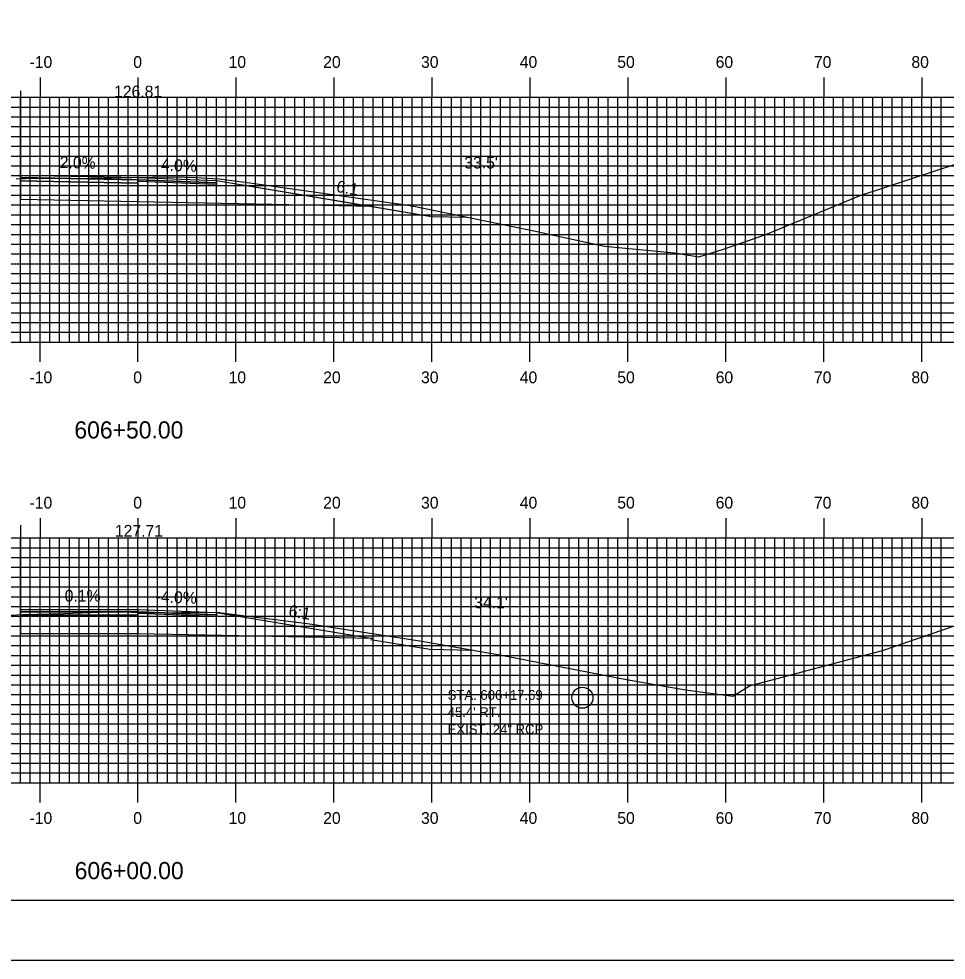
# Model space of a CAD drawing. Extents: x 842569 to 842912, y 363538 to 363758.
# Drawn here: x 842722.2 to 842816.9, y 363537.6 to 363633.7 of the extents above; entities that cross this region are included whole.
import ezdxf

# ---------------------------------------------------------------- set-up
doc = ezdxf.new("R2010")
doc.units = 0
for name, color, linetype in [('ANNOTATION', 7, 'Continuous'), ('BORDER', 7, 'Continuous'), ('D_Drainage_Culvert', 7, 'Continuous'), ('D_Roadway_Centerline', 7, 'Continuous'), ('D_Roadway_Centerline_Text', 7, 'Continuous'), ('D_Roadway_Edge_Shoulder', 7, 'Continuous'), ('D_Roadway_Edge_TW', 7, 'Continuous'), ('D_Roadway_FinishedGrade', 7, 'Continuous'), ('D_Roadway_Pavement', 7, 'Continuous'), ('D_Roadway_SlopeLines', 7, 'Continuous'), ('D_Roadway_SubGrade', 7, 'Continuous'), ('D_Text_Monospaced', 7, 'Continuous'), ('D_Text_Standard', 7, 'Continuous'), ('H_V ANNOTATION', 7, 'Continuous'), ('M_Roadway_Centerline', 7, 'Continuous'), ('MAJOR', 7, 'Continuous'), ('MINOR', 7, 'Continuous'), ('PLOT BOUNDARY', 7, 'Continuous'), ('S_Roadway_Centerline', 7, 'Continuous')]:
    doc.layers.add(name, color=color, linetype=linetype)

msp = doc.modelspace()

# ---------------------------------------------------------------- linework, layer by layer
at = {"layer": 'BORDER'}
msp.add_lwpolyline([(842584.798, 363543.721), (842904.798, 363543.721), (842904.798, 363753.721), (842584.798, 363753.721)], close=True, dxfattribs=at)
at = {"layer": 'D_Drainage_Culvert'}
msp.add_circle((842779.767, 363564.404), 1.074, dxfattribs=at)
at = {"layer": 'D_Roadway_Centerline'}
for points in [[(842722.398, 363617.776), (842734.398, 363617.536), (842742.398, 363617.216), (842758.352, 363614.557), (842764.352, 363613.557)], [(842722.398, 363573.413), (842734.398, 363573.429), (842742.398, 363573.109), (842758.352, 363570.45)]]:
    msp.add_lwpolyline(points, dxfattribs=at)
at = {"layer": 'D_Roadway_Edge_Shoulder'}
for points in [[(842734.398, 363617.536), (842742.398, 363617.216), (842742.398, 363616.966), (842734.398, 363617.286)], [(842734.398, 363573.429), (842742.398, 363573.109), (842742.398, 363572.859), (842734.398, 363573.179)]]:
    msp.add_lwpolyline(points, close=True, dxfattribs=at)
at = {"layer": 'D_Roadway_Edge_TW'}
for points in [[(842722.398, 363617.776), (842734.398, 363617.536), (842734.398, 363617.286), (842722.398, 363617.526)], [(842722.398, 363573.413), (842734.398, 363573.429), (842734.398, 363573.179), (842722.398, 363573.163)]]:
    msp.add_lwpolyline(points, close=True, dxfattribs=at)
for points in [[(842722.398, 363617.776), (842722.398, 363617.526)], [(842722.398, 363573.413), (842722.398, 363573.163)]]:
    msp.add_lwpolyline(points, dxfattribs=at)
at = {"layer": 'D_Roadway_FinishedGrade'}
for points in [[(842758.352, 363614.557), (842764.352, 363613.557), (842767.934, 363613.485)], [(842758.179, 363570.358), (842764.179, 363569.358), (842768.466, 363569.272)]]:
    msp.add_lwpolyline(points, dxfattribs=at)
at = {"layer": 'D_Roadway_Pavement'}
for points in [[(842722.398, 363617.526), (842722.398, 363617.193)], [(842734.398, 363617.286), (842734.398, 363616.953)], [(842734.398, 363617.286), (842734.398, 363616.953)], [(842722.398, 363573.163), (842722.398, 363572.83)], [(842734.398, 363573.179), (842734.398, 363572.845)], [(842734.398, 363573.179), (842734.398, 363572.845)]]:
    msp.add_lwpolyline(points, dxfattribs=at)
for points in [[(842722.398, 363617.526), (842734.398, 363617.286), (842734.398, 363616.953), (842722.398, 363617.193)], [(842734.398, 363617.286), (842742.398, 363616.966), (842742.398, 363616.799), (842734.398, 363617.119)], [(842722.398, 363573.163), (842734.398, 363573.179), (842734.398, 363572.845), (842722.398, 363572.83)], [(842734.398, 363573.179), (842742.398, 363572.859), (842742.398, 363572.692), (842734.398, 363573.012)]]:
    msp.add_lwpolyline(points, close=True, dxfattribs=at)
at = {"layer": 'D_Roadway_SlopeLines'}
msp.add_lwpolyline([(842742.398, 363617.216), (842764.352, 363613.557)], dxfattribs=at)
at = {"layer": 'D_Roadway_SubGrade'}
for p, q in [((842722.398, 363626.373), (842722.398, 363615.276)), ((842722.398, 363582.011), (842722.398, 363570.913))]:
    msp.add_line(p, q, dxfattribs=at)
for points in [[(842722.398, 363617.193), (842722.398, 363615.276)], [(842722.398, 363572.83), (842722.398, 363570.913)]]:
    msp.add_lwpolyline(points, dxfattribs=at)
for points in [[(842722.398, 363617.193), (842734.398, 363616.953), (842734.398, 363615.036), (842722.398, 363615.276)], [(842734.398, 363616.953), (842734.398, 363617.286), (842742.398, 363616.966), (842742.398, 363617.216), (842758.352, 363614.557), (842734.398, 363615.036)], [(842722.398, 363572.83), (842734.398, 363572.845), (842734.398, 363570.929), (842722.398, 363570.913)], [(842734.398, 363572.845), (842734.398, 363573.179), (842742.398, 363572.859), (842742.398, 363573.109), (842758.352, 363570.45), (842734.398, 363570.929)]]:
    msp.add_lwpolyline(points, close=True, dxfattribs=at)
at = {"layer": 'MAJOR'}
for p, q in [((842724.398, 363627.725), (842724.398, 363625.721)), ((842734.398, 363627.725), (842734.398, 363625.721)), ((842744.398, 363627.725), (842744.398, 363625.721)), ((842754.398, 363627.725), (842754.398, 363625.721)), ((842764.398, 363627.725), (842764.398, 363625.721)), ((842774.398, 363627.725), (842774.398, 363625.721)), ((842784.398, 363627.725), (842784.398, 363625.721)), ((842794.398, 363627.725), (842794.398, 363625.721)), ((842804.398, 363627.725), (842804.398, 363625.721)), ((842814.398, 363627.725), (842814.398, 363625.721)), ((842594.398, 363625.721), (842874.398, 363625.721)), ((842594.398, 363625.721), (842874.398, 363625.721)), ((842724.398, 363600.721), (842724.398, 363625.721)), ((842734.398, 363600.721), (842734.398, 363625.721)), ((842744.398, 363600.721), (842744.398, 363625.721)), ((842754.398, 363600.721), (842754.398, 363625.721)), ((842764.398, 363600.721), (842764.398, 363625.721)), ((842774.398, 363600.721), (842774.398, 363625.721)), ((842784.398, 363600.721), (842784.398, 363625.721)), ((842794.398, 363600.721), (842794.398, 363625.721)), ((842804.398, 363600.721), (842804.398, 363625.721)), ((842814.398, 363600.721), (842814.398, 363625.721)), ((842594.398, 363620.721), (842874.398, 363620.721)), ((842594.398, 363615.721), (842874.398, 363615.721)), ((842594.398, 363610.721), (842874.398, 363610.721)), ((842594.398, 363605.721), (842874.398, 363605.721)), ((842594.398, 363600.721), (842874.398, 363600.721)), ((842594.398, 363600.721), (842874.398, 363600.721)), ((842724.398, 363598.717), (842724.398, 363600.721)), ((842734.398, 363598.717), (842734.398, 363600.721)), ((842744.398, 363598.717), (842744.398, 363600.721)), ((842754.398, 363598.717), (842754.398, 363600.721)), ((842764.398, 363598.717), (842764.398, 363600.721)), ((842774.398, 363598.717), (842774.398, 363600.721)), ((842784.398, 363598.717), (842784.398, 363600.721)), ((842794.398, 363598.717), (842794.398, 363600.721)), ((842804.398, 363598.717), (842804.398, 363600.721)), ((842814.398, 363598.717), (842814.398, 363600.721)), ((842724.398, 363582.725), (842724.398, 363580.721)), ((842734.398, 363582.725), (842734.398, 363580.721)), ((842744.398, 363582.725), (842744.398, 363580.721)), ((842754.398, 363582.725), (842754.398, 363580.721)), ((842764.398, 363582.725), (842764.398, 363580.721)), ((842774.398, 363582.725), (842774.398, 363580.721)), ((842784.398, 363582.725), (842784.398, 363580.721)), ((842794.398, 363582.725), (842794.398, 363580.721)), ((842804.398, 363582.725), (842804.398, 363580.721)), ((842814.398, 363582.725), (842814.398, 363580.721)), ((842594.398, 363580.721), (842874.398, 363580.721)), ((842594.398, 363580.721), (842874.398, 363580.721)), ((842724.398, 363555.721), (842724.398, 363580.721)), ((842734.398, 363555.721), (842734.398, 363580.721)), ((842744.398, 363555.721), (842744.398, 363580.721)), ((842754.398, 363555.721), (842754.398, 363580.721)), ((842764.398, 363555.721), (842764.398, 363580.721)), ((842774.398, 363555.721), (842774.398, 363580.721)), ((842784.398, 363555.721), (842784.398, 363580.721)), ((842794.398, 363555.721), (842794.398, 363580.721)), ((842804.398, 363555.721), (842804.398, 363580.721)), ((842814.398, 363555.721), (842814.398, 363580.721)), ((842594.398, 363575.721), (842874.398, 363575.721)), ((842594.398, 363570.721), (842874.398, 363570.721)), ((842594.398, 363565.721), (842874.398, 363565.721)), ((842594.398, 363560.721), (842874.398, 363560.721)), ((842594.398, 363555.721), (842874.398, 363555.721)), ((842594.398, 363555.721), (842874.398, 363555.721)), ((842724.398, 363553.717), (842724.398, 363555.721)), ((842734.398, 363553.717), (842734.398, 363555.721)), ((842744.398, 363553.717), (842744.398, 363555.721)), ((842754.398, 363553.717), (842754.398, 363555.721)), ((842764.398, 363553.717), (842764.398, 363555.721)), ((842774.398, 363553.717), (842774.398, 363555.721)), ((842784.398, 363553.717), (842784.398, 363555.721)), ((842794.398, 363553.717), (842794.398, 363555.721)), ((842804.398, 363553.717), (842804.398, 363555.721)), ((842814.398, 363553.717), (842814.398, 363555.721))]:
    msp.add_line(p, q, dxfattribs=at)
at = {"layer": 'MINOR'}
for p, q in [((842722.398, 363600.721), (842722.398, 363625.721)), ((842723.398, 363600.721), (842723.398, 363625.721)), ((842725.398, 363600.721), (842725.398, 363625.721)), ((842726.398, 363600.721), (842726.398, 363625.721)), ((842727.398, 363600.721), (842727.398, 363625.721)), ((842728.398, 363600.721), (842728.398, 363625.721)), ((842729.398, 363600.721), (842729.398, 363625.721)), ((842730.398, 363600.721), (842730.398, 363625.721)), ((842731.398, 363600.721), (842731.398, 363625.721)), ((842732.398, 363600.721), (842732.398, 363625.721)), ((842733.398, 363600.721), (842733.398, 363625.721)), ((842735.398, 363600.721), (842735.398, 363625.721)), ((842736.398, 363600.721), (842736.398, 363625.721)), ((842737.398, 363600.721), (842737.398, 363625.721)), ((842738.398, 363600.721), (842738.398, 363625.721)), ((842739.398, 363600.721), (842739.398, 363625.721)), ((842740.398, 363600.721), (842740.398, 363625.721)), ((842741.398, 363600.721), (842741.398, 363625.721)), ((842742.398, 363600.721), (842742.398, 363625.721)), ((842743.398, 363600.721), (842743.398, 363625.721)), ((842745.398, 363600.721), (842745.398, 363625.721)), ((842746.398, 363600.721), (842746.398, 363625.721)), ((842747.398, 363600.721), (842747.398, 363625.721)), ((842748.398, 363600.721), (842748.398, 363625.721)), ((842749.398, 363600.721), (842749.398, 363625.721)), ((842750.398, 363600.721), (842750.398, 363625.721)), ((842751.398, 363600.721), (842751.398, 363625.721)), ((842752.398, 363600.721), (842752.398, 363625.721)), ((842753.398, 363600.721), (842753.398, 363625.721)), ((842755.398, 363600.721), (842755.398, 363625.721)), ((842756.398, 363600.721), (842756.398, 363625.721)), ((842757.398, 363600.721), (842757.398, 363625.721)), ((842758.398, 363600.721), (842758.398, 363625.721)), ((842759.398, 363600.721), (842759.398, 363625.721)), ((842760.398, 363600.721), (842760.398, 363625.721)), ((842761.398, 363600.721), (842761.398, 363625.721)), ((842762.398, 363600.721), (842762.398, 363625.721)), ((842763.398, 363600.721), (842763.398, 363625.721)), ((842765.398, 363600.721), (842765.398, 363625.721)), ((842766.398, 363600.721), (842766.398, 363625.721)), ((842767.398, 363600.721), (842767.398, 363625.721)), ((842768.398, 363600.721), (842768.398, 363625.721)), ((842769.398, 363600.721), (842769.398, 363625.721)), ((842770.398, 363600.721), (842770.398, 363625.721)), ((842771.398, 363600.721), (842771.398, 363625.721)), ((842772.398, 363600.721), (842772.398, 363625.721)), ((842773.398, 363600.721), (842773.398, 363625.721)), ((842775.398, 363600.721), (842775.398, 363625.721)), ((842776.398, 363600.721), (842776.398, 363625.721)), ((842777.398, 363600.721), (842777.398, 363625.721)), ((842778.398, 363600.721), (842778.398, 363625.721)), ((842779.398, 363600.721), (842779.398, 363625.721)), ((842780.398, 363600.721), (842780.398, 363625.721)), ((842781.398, 363600.721), (842781.398, 363625.721)), ((842782.398, 363600.721), (842782.398, 363625.721)), ((842783.398, 363600.721), (842783.398, 363625.721)), ((842785.398, 363600.721), (842785.398, 363625.721)), ((842786.398, 363600.721), (842786.398, 363625.721)), ((842787.398, 363600.721), (842787.398, 363625.721)), ((842788.398, 363600.721), (842788.398, 363625.721)), ((842789.398, 363600.721), (842789.398, 363625.721)), ((842790.398, 363600.721), (842790.398, 363625.721)), ((842791.398, 363600.721), (842791.398, 363625.721)), ((842792.398, 363600.721), (842792.398, 363625.721)), ((842793.398, 363600.721), (842793.398, 363625.721)), ((842795.398, 363600.721), (842795.398, 363625.721)), ((842796.398, 363600.721), (842796.398, 363625.721)), ((842797.398, 363600.721), (842797.398, 363625.721)), ((842798.398, 363600.721), (842798.398, 363625.721)), ((842799.398, 363600.721), (842799.398, 363625.721)), ((842800.398, 363600.721), (842800.398, 363625.721)), ((842801.398, 363600.721), (842801.398, 363625.721)), ((842802.398, 363600.721), (842802.398, 363625.721)), ((842803.398, 363600.721), (842803.398, 363625.721)), ((842805.398, 363600.721), (842805.398, 363625.721)), ((842806.398, 363600.721), (842806.398, 363625.721)), ((842807.398, 363600.721), (842807.398, 363625.721)), ((842808.398, 363600.721), (842808.398, 363625.721)), ((842809.398, 363600.721), (842809.398, 363625.721)), ((842810.398, 363600.721), (842810.398, 363625.721)), ((842811.398, 363600.721), (842811.398, 363625.721)), ((842812.398, 363600.721), (842812.398, 363625.721)), ((842813.398, 363600.721), (842813.398, 363625.721)), ((842815.398, 363600.721), (842815.398, 363625.721)), ((842816.398, 363600.721), (842816.398, 363625.721)), ((842594.398, 363624.721), (842874.398, 363624.721)), ((842594.398, 363623.721), (842874.398, 363623.721)), ((842594.398, 363622.721), (842874.398, 363622.721)), ((842594.398, 363621.721), (842874.398, 363621.721)), ((842594.398, 363619.721), (842874.398, 363619.721)), ((842594.398, 363618.721), (842874.398, 363618.721)), ((842594.398, 363617.721), (842874.398, 363617.721)), ((842594.398, 363616.721), (842874.398, 363616.721)), ((842594.398, 363614.721), (842874.398, 363614.721)), ((842594.398, 363613.721), (842874.398, 363613.721)), ((842594.398, 363612.721), (842874.398, 363612.721)), ((842594.398, 363611.721), (842874.398, 363611.721)), ((842594.398, 363609.721), (842874.398, 363609.721)), ((842594.398, 363608.721), (842874.398, 363608.721)), ((842594.398, 363607.721), (842874.398, 363607.721)), ((842594.398, 363606.721), (842874.398, 363606.721)), ((842594.398, 363604.721), (842874.398, 363604.721)), ((842594.398, 363603.721), (842874.398, 363603.721)), ((842594.398, 363602.721), (842874.398, 363602.721)), ((842594.398, 363601.721), (842874.398, 363601.721)), ((842722.398, 363555.721), (842722.398, 363580.721)), ((842723.398, 363555.721), (842723.398, 363580.721)), ((842725.398, 363555.721), (842725.398, 363580.721)), ((842726.398, 363555.721), (842726.398, 363580.721)), ((842727.398, 363555.721), (842727.398, 363580.721)), ((842728.398, 363555.721), (842728.398, 363580.721)), ((842729.398, 363555.721), (842729.398, 363580.721)), ((842730.398, 363555.721), (842730.398, 363580.721)), ((842731.398, 363555.721), (842731.398, 363580.721)), ((842732.398, 363555.721), (842732.398, 363580.721)), ((842733.398, 363555.721), (842733.398, 363580.721)), ((842735.398, 363555.721), (842735.398, 363580.721)), ((842736.398, 363555.721), (842736.398, 363580.721)), ((842737.398, 363555.721), (842737.398, 363580.721)), ((842738.398, 363555.721), (842738.398, 363580.721)), ((842739.398, 363555.721), (842739.398, 363580.721)), ((842740.398, 363555.721), (842740.398, 363580.721)), ((842741.398, 363555.721), (842741.398, 363580.721)), ((842742.398, 363555.721), (842742.398, 363580.721)), ((842743.398, 363555.721), (842743.398, 363580.721)), ((842745.398, 363555.721), (842745.398, 363580.721)), ((842746.398, 363555.721), (842746.398, 363580.721)), ((842747.398, 363555.721), (842747.398, 363580.721)), ((842748.398, 363555.721), (842748.398, 363580.721)), ((842749.398, 363555.721), (842749.398, 363580.721)), ((842750.398, 363555.721), (842750.398, 363580.721)), ((842751.398, 363555.721), (842751.398, 363580.721)), ((842752.398, 363555.721), (842752.398, 363580.721)), ((842753.398, 363555.721), (842753.398, 363580.721)), ((842755.398, 363555.721), (842755.398, 363580.721)), ((842756.398, 363555.721), (842756.398, 363580.721)), ((842757.398, 363555.721), (842757.398, 363580.721)), ((842758.398, 363555.721), (842758.398, 363580.721)), ((842759.398, 363555.721), (842759.398, 363580.721)), ((842760.398, 363555.721), (842760.398, 363580.721)), ((842761.398, 363555.721), (842761.398, 363580.721)), ((842762.398, 363555.721), (842762.398, 363580.721)), ((842763.398, 363555.721), (842763.398, 363580.721)), ((842765.398, 363555.721), (842765.398, 363580.721)), ((842766.398, 363555.721), (842766.398, 363580.721)), ((842767.398, 363555.721), (842767.398, 363580.721)), ((842768.398, 363555.721), (842768.398, 363580.721)), ((842769.398, 363555.721), (842769.398, 363580.721)), ((842770.398, 363555.721), (842770.398, 363580.721)), ((842771.398, 363555.721), (842771.398, 363580.721)), ((842772.398, 363555.721), (842772.398, 363580.721)), ((842773.398, 363555.721), (842773.398, 363580.721)), ((842775.398, 363555.721), (842775.398, 363580.721)), ((842776.398, 363555.721), (842776.398, 363580.721)), ((842777.398, 363555.721), (842777.398, 363580.721)), ((842778.398, 363555.721), (842778.398, 363580.721)), ((842779.398, 363555.721), (842779.398, 363580.721)), ((842780.398, 363555.721), (842780.398, 363580.721)), ((842781.398, 363555.721), (842781.398, 363580.721)), ((842782.398, 363555.721), (842782.398, 363580.721)), ((842783.398, 363555.721), (842783.398, 363580.721)), ((842785.398, 363555.721), (842785.398, 363580.721)), ((842786.398, 363555.721), (842786.398, 363580.721)), ((842787.398, 363555.721), (842787.398, 363580.721)), ((842788.398, 363555.721), (842788.398, 363580.721)), ((842789.398, 363555.721), (842789.398, 363580.721)), ((842790.398, 363555.721), (842790.398, 363580.721)), ((842791.398, 363555.721), (842791.398, 363580.721)), ((842792.398, 363555.721), (842792.398, 363580.721)), ((842793.398, 363555.721), (842793.398, 363580.721)), ((842795.398, 363555.721), (842795.398, 363580.721)), ((842796.398, 363555.721), (842796.398, 363580.721)), ((842797.398, 363555.721), (842797.398, 363580.721)), ((842798.398, 363555.721), (842798.398, 363580.721)), ((842799.398, 363555.721), (842799.398, 363580.721)), ((842800.398, 363555.721), (842800.398, 363580.721)), ((842801.398, 363555.721), (842801.398, 363580.721)), ((842802.398, 363555.721), (842802.398, 363580.721)), ((842803.398, 363555.721), (842803.398, 363580.721)), ((842805.398, 363555.721), (842805.398, 363580.721)), ((842806.398, 363555.721), (842806.398, 363580.721)), ((842807.398, 363555.721), (842807.398, 363580.721)), ((842808.398, 363555.721), (842808.398, 363580.721)), ((842809.398, 363555.721), (842809.398, 363580.721)), ((842810.398, 363555.721), (842810.398, 363580.721)), ((842811.398, 363555.721), (842811.398, 363580.721)), ((842812.398, 363555.721), (842812.398, 363580.721)), ((842813.398, 363555.721), (842813.398, 363580.721)), ((842815.398, 363555.721), (842815.398, 363580.721)), ((842816.398, 363555.721), (842816.398, 363580.721)), ((842594.398, 363579.721), (842874.398, 363579.721)), ((842594.398, 363578.721), (842874.398, 363578.721)), ((842594.398, 363577.721), (842874.398, 363577.721)), ((842594.398, 363576.721), (842874.398, 363576.721)), ((842594.398, 363574.721), (842874.398, 363574.721)), ((842594.398, 363573.721), (842874.398, 363573.721)), ((842594.398, 363572.721), (842874.398, 363572.721)), ((842594.398, 363571.721), (842874.398, 363571.721)), ((842594.398, 363569.721), (842874.398, 363569.721)), ((842594.398, 363568.721), (842874.398, 363568.721)), ((842594.398, 363567.721), (842874.398, 363567.721)), ((842594.398, 363566.721), (842874.398, 363566.721)), ((842594.398, 363564.721), (842874.398, 363564.721)), ((842594.398, 363563.721), (842874.398, 363563.721)), ((842594.398, 363562.721), (842874.398, 363562.721)), ((842594.398, 363561.721), (842874.398, 363561.721)), ((842594.398, 363559.721), (842874.398, 363559.721)), ((842594.398, 363558.721), (842874.398, 363558.721)), ((842594.398, 363557.721), (842874.398, 363557.721)), ((842594.398, 363556.721), (842874.398, 363556.721))]:
    msp.add_line(p, q, dxfattribs=at)
at = {"layer": 'PLOT BOUNDARY'}
msp.add_lwpolyline([(842568.611, 363537.603), (842908.611, 363537.603), (842908.611, 363757.603), (842568.611, 363757.603)], close=True, dxfattribs=at)
at = {"layer": 'S_Roadway_Centerline'}
for points in [[(842721.971, 363617.394), (842722.429, 363617.41), (842722.496, 363617.412), (842722.904, 363617.409), (842729.583, 363617.447), (842737.982, 363617.585), (842740.27, 363617.522), (842742.701, 363617.397), (842745.825, 363616.99), (842762.19, 363614.652), (842762.255, 363614.644), (842762.297, 363614.636), (842762.374, 363614.62), (842774.814, 363612.081), (842782.038, 363610.506), (842789.177, 363609.822), (842791.666, 363609.428), (842794.161, 363610.199), (842798.48, 363611.717), (842808.109, 363615.69), (842818.05, 363618.967)], [(842714.747, 363572.471), (842722.633, 363572.897), (842726.809, 363573.013), (842732.419, 363573.194), (842735.014, 363573.088), (842742.618, 363573.139), (842742.909, 363573.078), (842750.574, 363572.134), (842751.687, 363571.983), (842763.388, 363570.175), (842771.512, 363568.763), (842784.256, 363566.248), (842790.297, 363565.206), (842795.137, 363564.57), (842796.81, 363565.629), (842810.416, 363569.237), (842822.719, 363573.436), (842828.267, 363573.503), (842835.487, 363572.347), (842848.826, 363572.658), (842859.64, 363572.272), (842865.612, 363571.957), (842874.398, 363571.619)]]:
    msp.add_lwpolyline(points, dxfattribs=at)

# ---------------------------------------------------------------- texts
at = {"layer": 'ANNOTATION'}
for s, rotation, p in [('2.0%', 358.85424, (842726.405, 363618.496)), ('-4.0%', 357.70939, (842736.19, 363618.266)), ('6:1', 350.53749, (842754.59, 363616.06)), ('-0.1%', 0.07309, (842726.384, 363574.218)), ('-4.0%', 357.70939, (842736.19, 363574.159)), ('6:1', 350.53749, (842749.708, 363572.718))]:
    msp.add_text(s, height=1.2, rotation=rotation, dxfattribs=at).set_placement(p)
at = {"layer": 'D_Roadway_Centerline_Text'}
for s, p in [('126.81', (842731.958, 363625.705)), ('127.71', (842732.043, 363580.846))]:
    msp.add_text(s, height=1.2, dxfattribs=at).set_placement(p)
at = {"layer": 'D_Text_Monospaced'}
for s, height, p in [('STA. 606+17.69', 0.99996, (842766.008, 363564.186)), ("45.4' RT.", 1, (842766.008, 363562.436)), ('EXIST. 24" RCP', 0.99996, (842766.008, 363560.686))]:
    msp.add_text(s, height=height, dxfattribs=at).set_placement(p)
at = {"layer": 'D_Text_Standard'}
for s, p in [("33.5'", (842767.707, 363618.446)), ("34.1'", (842768.731, 363573.532))]:
    msp.add_text(s, height=1.2, dxfattribs=at).set_placement(p)
at = {"layer": 'H_V ANNOTATION'}
for s, height, p in [('-10', 1.2, (842723.328, 363628.721)), ('0', 1.2, (842733.916, 363628.721)), ('10', 1.2, (842743.649, 363628.721)), ('20', 1.2, (842753.306, 363628.721)), ('30', 1.2, (842763.295, 363628.721)), ('40', 1.2, (842773.37, 363628.721)), ('50', 1.2, (842783.327, 363628.721)), ('60', 1.2, (842793.37, 363628.721)), ('70', 1.2, (842803.402, 363628.721)), ('80', 1.2, (842813.349, 363628.721)), ('-10', 1.2, (842723.328, 363596.521)), ('0', 1.2, (842733.916, 363596.521)), ('10', 1.2, (842743.649, 363596.521)), ('20', 1.2, (842753.306, 363596.521)), ('30', 1.2, (842763.295, 363596.521)), ('40', 1.2, (842773.37, 363596.521)), ('50', 1.2, (842783.327, 363596.521)), ('60', 1.2, (842793.37, 363596.521)), ('70', 1.2, (842803.402, 363596.521)), ('80', 1.2, (842813.349, 363596.521)), ('606+50.00', 1.75, (842727.906, 363590.877)), ('-10', 1.2, (842723.328, 363583.721)), ('0', 1.2, (842733.916, 363583.721)), ('10', 1.2, (842743.649, 363583.721)), ('20', 1.2, (842753.306, 363583.721)), ('30', 1.2, (842763.295, 363583.721)), ('40', 1.2, (842773.37, 363583.721)), ('50', 1.2, (842783.327, 363583.721)), ('60', 1.2, (842793.37, 363583.721)), ('70', 1.2, (842803.402, 363583.721)), ('80', 1.2, (842813.349, 363583.721)), ('-10', 1.2, (842723.328, 363551.521)), ('0', 1.2, (842733.916, 363551.521)), ('10', 1.2, (842743.649, 363551.521)), ('20', 1.2, (842753.306, 363551.521)), ('30', 1.2, (842763.295, 363551.521)), ('40', 1.2, (842773.37, 363551.521)), ('50', 1.2, (842783.327, 363551.521)), ('60', 1.2, (842793.37, 363551.521)), ('70', 1.2, (842803.402, 363551.521)), ('80', 1.2, (842813.349, 363551.521)), ('606+00.00', 1.75, (842727.937, 363545.877))]:
    msp.add_text(s, height=height, dxfattribs=at).set_placement(p)
at = {"layer": 'M_Roadway_Centerline'}
for s, p in [('C', (842722.49, 363617.412)), ('L', (842722.496, 363617.404)), ('C', (842722.628, 363572.897)), ('L', (842722.633, 363572.889))]:
    msp.add_text(s, height=0.0146, dxfattribs=at).set_placement(p)

doc.saveas('drawing.dxf')
